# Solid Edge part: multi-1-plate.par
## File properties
Author: Deepak Maini
Template: Normal.par
Last saved by: MYPC
Revision: 5
Application: Solid Edge
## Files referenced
..\multi-cutout.asm
ED:\sld-edg-15\cd-models\c09-sld-edg-15\figure28-8&29\multi-cutout.asm
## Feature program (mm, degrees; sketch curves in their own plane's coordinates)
sketch for "unnamed Protrusion 1" plane through (0, 0, 0) normal (0, 0, 1) x-axis (1, 0, 0)
  arc centre (-57, 0) radius 14.3058 from (-63.4487, -12.7699) to (-63.4487, 12.7699) cw
  line (-63.4487, 12.7699) -> (-18.031, 35.7055)
  arc centre (0, 0) radius 40 from (-18.031, 35.7055) to (18.1555, 35.6424) cw
  line (18.1555, 35.6424) -> (63.4127, 12.5893)
  arc centre (57, 0) radius 14.1284 from (63.4127, 12.5893) to (63.4127, -12.5893) cw
  line (63.4127, -12.5893) -> (18.1555, -35.6424)
  arc centre (0, 0) radius 40 from (18.1555, -35.6424) to (-18.031, -35.7055) cw
  line (-63.4487, -12.7699) -> (-18.031, -35.7055)
extrude "unnamed Protrusion 1" add finite 6.5 symmetric
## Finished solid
Body 1: solid body, 10 faces, 24 edges, 16 vertices.
  Faces by surface: plane 6, cylinder 4
  Edges by curve: line 16, circle 8
Bounding box of the edges (mm): 142.434 x 80.000 x 6.500, from (-71.3058, -40, -3.25) to (71.1284, 40, 3.25).
Cylindrical faces by radius (mm): R14.1284 x1, R14.3058 x1, R40 x2
Planar faces by outward normal: +z 1, -z 1, oblique 4
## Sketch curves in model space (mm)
arc centre (0, 0, 0) radius 40 from (-18.031, 35.7055, 0) through (0.0698, 39.9999, 0) to (18.1555, 35.6424, 0)
line (18.1555, 35.6424, 0) -> (63.4127, 12.5893, 0)
arc centre (57, 0, 0) radius 14.1284 from (63.4127, 12.5893, 0) through (71.1222, -0.4198, 0) to (63.4127, -12.5893, 0)
line (63.4127, -12.5893, 0) -> (18.1555, -35.6424, 0)
arc centre (0, 0, 0) radius 40 from (18.1555, -35.6424, 0) through (0.0698, -39.9999, 0) to (-18.031, -35.7055, 0)
line (-63.4487, -12.7699, 0) -> (-18.031, -35.7055, 0)
arc centre (-57, 0, 0) radius 14.3058 from (-63.4487, -12.7699, 0) through (-71.2995, 0.4265, 0) to (-63.4487, 12.7699, 0)
line (-63.4487, 12.7699, 0) -> (-18.031, 35.7055, 0)
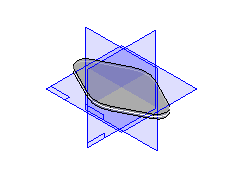
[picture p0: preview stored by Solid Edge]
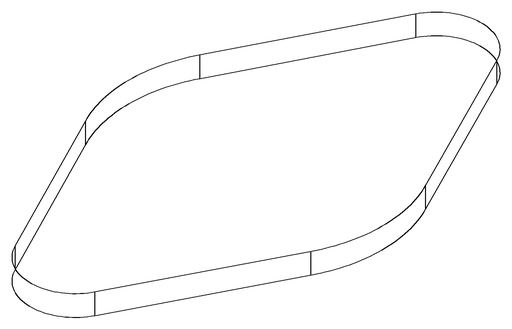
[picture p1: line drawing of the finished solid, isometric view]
